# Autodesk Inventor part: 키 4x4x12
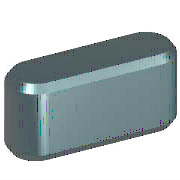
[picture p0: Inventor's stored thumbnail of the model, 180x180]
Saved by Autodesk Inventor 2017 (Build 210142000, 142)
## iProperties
IsCustomPart: 1
Created: 2012-02
Part Number: 키 4x4x12
Material: 강철, 연강
Description: 키 및 해당 키홈
Document SubType Name: Modeling
Standard: KS B 1311
Designer: mduedu
Standards Organization: KS
Language: ko-KR
Size Designation: 4 x 4 x 12
Categories: <MemberInstance><Categories><Category DisplayName="샤프트 부품" InternalName="7f7aeb1f-a693-4053-b835-cee3144e0d98" Mnemonic="SHFT"><Category DisplayName="키" Interna
Density: 7.85 g/cm^3
Appearance: 노란색
Mass: 1.38563 g
Surface Area: 1.94869 cm^2
Volume: 0.176513 cm^3
Author: mduedu
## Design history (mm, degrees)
workplane "Work Plane1"
workplane "Work Plane2"
sketch "스케치1"
  geometry: L1 (2, 2)-(10, 2); L2 (10, -2)-(2, -2); L3 (0, 9.4)-(0, -7.4) reference; L4 (-5, 0)-(30, 0) reference; L5 (12, 0)-(12, 7); A1 r 2 centre (2, 0) between (2, 2) and (2, -2); A2 r 2 centre (10, 0) between (10, -2) and (10, 2)
  constraints: 6 end point, 5 point on circle, 4 tangent, 3 point on line, 2 centre point, 1 horizontal, 1 parallel, 1 perpendicular
  dimensions: "d0" = 2 radius of A1 (= 0.5 x PB); "d13" = 2 radius of A2 (= 0.5 x PB); "d14" = 12 distance between parallel lines of L5 L3 (= NLG)
extrude "본체1" new body sketch "스케치1" taper "d3" = 0 deg; stored distance "d4" = 10
workplane "Work Plane3"
body "Solid1"
chamfer "모따기1" distance "d8" = 0.25 (= PHH); stored, may be unused: second distance "d9" = 0.25 (= PHH), angle "d15" = 45 deg
other parameters: "d1" = -2.5 (= -PNT), "d2" = 1.5 (= PH - PNT), "NLG" = 12 [user parameter; used in 3 equation terms], "PB" = 4 [user parameter; used in 2 equation terms], "PNT" = 2.5 [user parameter; used in 2 equation terms], "PH" = 4 [user parameter; used in 1 equation term], "PHH" = 0.25 [user parameter; used in 2 equation terms], "d10" = 0, "d16" = 0, "d17" = 0, "d18" = 0, "PLB2" = 12 (= NLG) [user parameter], "WDMAX" = 12 [user parameter], "PLB1" = 12 (= NLG) [user parameter], "RR" = 0.08 [user parameter], "PUEB" = 1.8 [user parameter]
